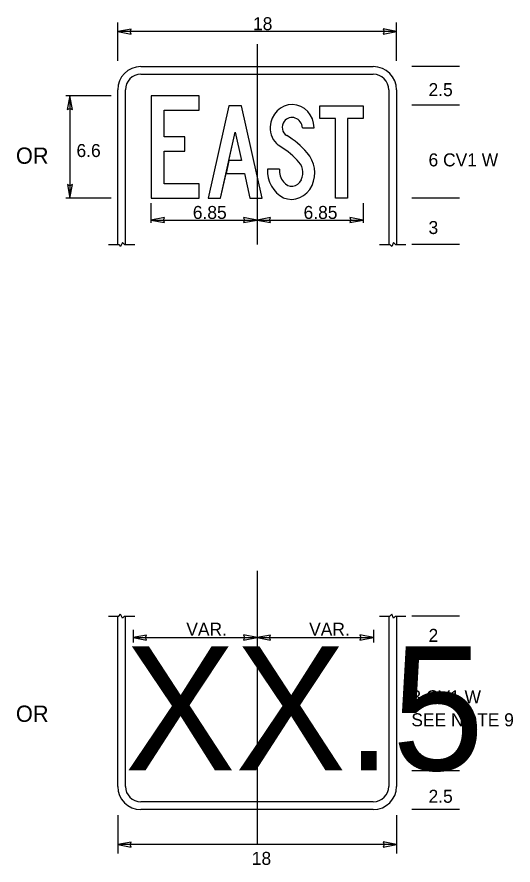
# Model space of a CAD drawing. Extents: x 56108 to 56738, y 11696 to 12112.
# Drawn here: x 56631.7 to 56738.5, y 11927.4 to 12110.1 of the extents above; entities that cross this region are included whole.
import ezdxf

# ---------------------------------------------------------------- set-up
doc = ezdxf.new("R2010")
doc.units = 0
for name, color, linetype in [('CL_dp', 7, 'Continuous'), ('GSDims', 7, 'Continuous'), ('SignPanel', 7, 'Continuous')]:
    doc.layers.add(name, color=color, linetype=linetype)

msp = doc.modelspace()

# ---------------------------------------------------------------- linework, layer by layer
at = {"layer": 'CL_dp'}
for p, q in [((56683.41, 12104.19), (56683.41, 12061.05)), ((56683.41, 11990.78), (56683.41, 11931.84))]:
    msp.add_line(p, q, dxfattribs=at)
at = {"layer": 'GSDims'}
for p, q in [((56653.41, 12100.62), (56653.41, 12108.84)), ((56713.41, 12100.62), (56713.41, 12108.84)), ((56656.31, 12107.46), (56653.41, 12106.92)), ((56713.41, 12106.92), (56653.41, 12106.92)), ((56653.41, 12106.92), (56656.31, 12106.36)), ((56656.09, 12106.92), (56656.31, 12107.46)), ((56656.31, 12106.36), (56656.09, 12106.92)), ((56713.41, 12106.92), (56710.51, 12107.48)), ((56710.51, 12107.48), (56710.73, 12106.92)), ((56710.73, 12106.92), (56710.51, 12106.38)), ((56710.51, 12106.38), (56713.41, 12106.92)), ((56726.96, 12099.38), (56716.67, 12099.38)), ((56652, 12093.05), (56642.26, 12093.05)), ((56643.13, 12093.05), (56642.57, 12090.15)), ((56643.13, 12093.05), (56643.13, 12071.05)), ((56643.67, 12090.15), (56643.13, 12093.05)), ((56642.57, 12090.15), (56643.13, 12090.37)), ((56643.13, 12090.37), (56643.67, 12090.15)), ((56726.96, 12091.05), (56716.67, 12091.05)), ((56643.13, 12073.73), (56642.59, 12073.95)), ((56642.59, 12073.95), (56643.13, 12071.05)), ((56643.13, 12071.05), (56643.69, 12073.95)), ((56643.69, 12073.95), (56643.13, 12073.73)), ((56652, 12071.05), (56642.26, 12071.05)), ((56726.96, 12071.05), (56716.67, 12071.05)), ((56660.58, 12069.96), (56660.58, 12065.71)), ((56706.25, 12069.96), (56706.25, 12065.71)), ((56663.48, 12066.87), (56660.58, 12066.33)), ((56663.26, 12066.33), (56663.48, 12066.87)), ((56683.41, 12066.33), (56680.51, 12066.89)), ((56680.51, 12066.89), (56680.73, 12066.33)), ((56686.31, 12066.87), (56683.41, 12066.33)), ((56686.09, 12066.33), (56686.31, 12066.87)), ((56706.25, 12066.33), (56703.35, 12066.89)), ((56703.35, 12066.89), (56703.57, 12066.33)), ((56660.58, 12066.33), (56683.41, 12066.33)), ((56660.58, 12066.33), (56663.48, 12065.77)), ((56663.48, 12065.77), (56663.26, 12066.33)), ((56680.73, 12066.33), (56680.51, 12065.79)), ((56680.51, 12065.79), (56683.41, 12066.33)), ((56683.41, 12066.33), (56706.25, 12066.33)), ((56683.41, 12066.33), (56686.31, 12065.77)), ((56686.31, 12065.77), (56686.09, 12066.33)), ((56703.57, 12066.33), (56703.35, 12065.79)), ((56703.35, 12065.79), (56706.25, 12066.33)), ((56726.96, 12061.05), (56716.67, 12061.05)), ((56726.96, 11981.05), (56716.67, 11981.05)), ((56656.74, 11978.07), (56656.74, 11975.38)), ((56708.43, 11978.07), (56708.43, 11975.38)), ((56659.64, 11976.96), (56656.74, 11976.42)), ((56656.74, 11976.42), (56683.41, 11976.42)), ((56656.74, 11976.42), (56659.64, 11975.86)), ((56659.42, 11976.42), (56659.64, 11976.96)), ((56659.64, 11975.86), (56659.42, 11976.42)), ((56683.41, 11976.42), (56680.51, 11976.98)), ((56680.51, 11976.98), (56680.73, 11976.42)), ((56680.73, 11976.42), (56680.51, 11975.88)), ((56680.51, 11975.88), (56683.41, 11976.42)), ((56686.31, 11976.96), (56683.41, 11976.42)), ((56683.41, 11976.42), (56708.43, 11976.42)), ((56683.41, 11976.42), (56686.31, 11975.86)), ((56686.09, 11976.42), (56686.31, 11976.96)), ((56686.31, 11975.86), (56686.09, 11976.42)), ((56708.43, 11976.42), (56705.53, 11976.98)), ((56705.53, 11976.98), (56705.75, 11976.42)), ((56705.75, 11976.42), (56705.53, 11975.88)), ((56705.53, 11975.88), (56708.43, 11976.42)), ((56726.96, 11974.38), (56716.67, 11974.38)), ((56726.96, 11947.71), (56716.67, 11947.71)), ((56726.96, 11939.38), (56716.67, 11939.38)), ((56653.41, 11938.14), (56653.41, 11929.91)), ((56713.41, 11938.14), (56713.41, 11929.91)), ((56656.31, 11932.38), (56653.41, 11931.84)), ((56713.41, 11931.84), (56653.41, 11931.84)), ((56653.41, 11931.84), (56656.31, 11931.28)), ((56656.09, 11931.84), (56656.31, 11932.38)), ((56656.31, 11931.28), (56656.09, 11931.84)), ((56713.41, 11931.84), (56710.51, 11932.4)), ((56710.51, 11932.4), (56710.73, 11931.84)), ((56710.73, 11931.84), (56710.51, 11931.3)), ((56710.51, 11931.3), (56713.41, 11931.84))]:
    msp.add_line(p, q, dxfattribs=at)
at = {"layer": 'SignPanel'}
for p, q in [((56693.15, 12086.17), (56695.69, 12086.17)), ((56693.15, 12086.17), (56695.69, 12086.17)), ((56693.15, 12086.17), (56695.69, 12086.17)), ((56688.21, 12077.3), (56685.62, 12077.3)), ((56688.21, 12077.3), (56685.62, 12077.3)), ((56688.21, 12077.3), (56685.62, 12077.3)), ((56654.45, 12061.46), (56654.04, 12060.63)), ((56654.45, 12061.46), (56654.87, 12061.05)), ((56712.79, 12061.46), (56712.37, 12060.63)), ((56712.79, 12061.46), (56713.2, 12061.05)), ((56651.41, 12061.05), (56653.63, 12061.05)), ((56653.63, 12061.05), (56654.04, 12060.63)), ((56654.87, 12061.05), (56657.08, 12061.05)), ((56709.75, 12061.05), (56711.96, 12061.05)), ((56711.96, 12061.05), (56712.37, 12060.63)), ((56713.2, 12061.05), (56715.41, 12061.05)), ((56651.41, 11981.05), (56653.63, 11981.05)), ((56653.63, 11981.05), (56654.04, 11981.46)), ((56654.45, 11980.63), (56654.04, 11981.46)), ((56654.45, 11980.63), (56654.87, 11981.05)), ((56654.87, 11981.05), (56657.08, 11981.05)), ((56709.75, 11981.05), (56711.96, 11981.05)), ((56711.96, 11981.05), (56712.37, 11981.46)), ((56712.79, 11980.63), (56712.37, 11981.46)), ((56712.79, 11980.63), (56713.2, 11981.05)), ((56713.2, 11981.05), (56715.41, 11981.05))]:
    msp.add_line(p, q, dxfattribs=at)
for points in [[(56658.41, 12099.38), (56708.41, 12099.38)], [(56658.41, 12097.71), (56708.41, 12097.71)], [(56653.41, 12061.05), (56653.41, 12094.38)], [(56655.08, 12061.05), (56655.08, 12094.38)], [(56711.75, 12094.38), (56711.75, 12061.05)], [(56713.41, 12094.38), (56713.41, 12061.05)], [(56653.41, 11944.38), (56653.41, 11981.05)], [(56655.08, 11944.38), (56655.08, 11981.05)], [(56711.75, 11981.05), (56711.75, 11944.38)], [(56713.41, 11981.05), (56713.41, 11944.38)], [(56708.41, 11941.05), (56658.41, 11941.05)], [(56708.41, 11939.38), (56658.41, 11939.38)]]:
    msp.add_lwpolyline(points, dxfattribs=at)
for points in [[(56663.44, 12074.14), (56663.44, 12081.19), (56667.87, 12081.19), (56667.87, 12084.27), (56663.44, 12084.27), (56663.44, 12089.99), (56670.93, 12089.99), (56670.93, 12093.08), (56660.61, 12093.08), (56660.61, 12071.06), (56670.93, 12071.06), (56670.93, 12074.14)], [(56663.44, 12074.14), (56663.44, 12081.19), (56667.87, 12081.19), (56667.87, 12084.27), (56663.44, 12084.27), (56663.44, 12089.99), (56670.93, 12089.99), (56670.93, 12093.08), (56660.61, 12093.08), (56660.61, 12071.06), (56670.93, 12071.06), (56670.93, 12074.14)], [(56663.44, 12074.14), (56663.44, 12081.19), (56667.87, 12081.19), (56667.87, 12084.27), (56663.44, 12084.27), (56663.44, 12089.99), (56670.93, 12089.99), (56670.93, 12093.08), (56660.61, 12093.08), (56660.61, 12071.06), (56670.93, 12071.06), (56670.93, 12074.14)], [(56680.7, 12076.39), (56681.88, 12071.06), (56684.52, 12071.06), (56680.08, 12090.95), (56677.34, 12090.95), (56672.91, 12071.06), (56675.54, 12071.06), (56676.73, 12076.39)], [(56677.35, 12079.17), (56676.73, 12076.39), (56680.7, 12076.39), (56681.88, 12071.06), (56684.52, 12071.06), (56680.08, 12090.95), (56677.34, 12090.95), (56672.91, 12071.06), (56675.54, 12071.06), (56678.71, 12085.29), (56680.08, 12079.17)], [(56677.35, 12079.17), (56676.73, 12076.39), (56680.7, 12076.39), (56681.88, 12071.06), (56684.52, 12071.06), (56680.08, 12090.95), (56677.34, 12090.95), (56672.91, 12071.06), (56675.54, 12071.06), (56678.71, 12085.29), (56680.08, 12079.17)], [(56700.3, 12088.17), (56696.92, 12088.17), (56696.92, 12090.95), (56706.25, 12090.95), (56706.25, 12088.17), (56702.86, 12088.17), (56702.86, 12071.06), (56700.3, 12071.06)], [(56700.3, 12088.17), (56696.92, 12088.17), (56696.92, 12090.95), (56706.25, 12090.95), (56706.25, 12088.17), (56702.86, 12088.17), (56702.86, 12071.06), (56700.3, 12071.06)], [(56700.3, 12088.17), (56696.92, 12088.17), (56696.92, 12090.95), (56706.25, 12090.95), (56706.25, 12088.17), (56702.86, 12088.17), (56702.86, 12071.06), (56700.3, 12071.06)], [(56678.71, 12085.29), (56680.08, 12079.17), (56677.35, 12079.17)]]:
    msp.add_lwpolyline(points, close=True, dxfattribs=at)
for centre, radius, start, end in [((56658.41, 12094.38), 5, 90, 180), ((56658.41, 12094.38), 3.33, 90, 180), ((56708.41, 12094.38), 5, 0, 90), ((56708.41, 12094.38), 3.33, 0, 90), ((56658.41, 11944.38), 5, 180, 270), ((56658.41, 11944.38), 3.33, 180, 270), ((56708.41, 11944.38), 5, 270, 360), ((56708.41, 11944.38), 3.33, 270, 360)]:
    msp.add_arc(centre, radius, start, end, dxfattribs=at)
for centre, major_axis, start_param, end_param in [((56690.95, 12086.05), (0, 5.16), 4.736267, 7.790596), ((56690.95, 12086.05), (0, 5.16), 4.736267, 7.790596), ((56690.95, 12086.05), (0, 5.16), 4.736267, 7.790596), ((56690.92, 12085.99), (0, 2.43), 4.786904, 7.140738), ((56690.92, 12085.99), (0, 2.43), 4.786904, 7.140738), ((56690.92, 12085.99), (0, 2.43), 4.786904, 7.140738), ((56690.65, 12086.29), (0, 2), 0.87378, 2.656959), ((56690.65, 12086.29), (0, 2), 0.87378, 2.656959), ((56690.65, 12086.29), (0, 2), 0.87378, 2.656959), ((56690.47, 12086.21), (0, 4.63), 1.534831, 2.511766), ((56690.47, 12086.21), (0, 4.63), 1.534831, 2.511766), ((56690.47, 12086.21), (0, 4.63), 1.534831, 2.511766), ((56681.36, 12067.78), (0, 19.09), 5.462886, 5.782242), ((56681.36, 12067.78), (0, 19.09), 5.462886, 5.782242), ((56681.36, 12067.78), (0, 19.09), 5.462886, 5.782242), ((56679.14, 12064.74), (0, 20.15), 5.515137, 5.786988), ((56679.14, 12064.74), (0, 20.15), 5.515137, 5.786988), ((56679.14, 12064.74), (0, 20.15), 5.515137, 5.786988), ((56690.14, 12076.49), (0, 6.17), 4.260987, 5.485755), ((56690.14, 12076.49), (0, 6.17), 4.260987, 5.485755), ((56690.14, 12076.49), (0, 6.17), 4.260987, 5.485755), ((56690.09, 12076.49), (0, 3.44), 4.254409, 5.632398), ((56690.09, 12076.49), (0, 3.44), 4.254409, 5.632398), ((56690.09, 12076.49), (0, 3.44), 4.254409, 5.632398), ((56691.6, 12077.01), (0, 6.5), 1.526364, 2.701682), ((56691.6, 12077.01), (0, 6.5), 1.526364, 2.701682), ((56691.6, 12077.01), (0, 6.5), 1.526364, 2.701682), ((56691.84, 12077.12), (0, 3.96), 1.524757, 2.28214), ((56691.84, 12077.12), (0, 3.96), 1.524757, 2.28214), ((56691.84, 12077.12), (0, 3.96), 1.524757, 2.28214), ((56690.88, 12076.14), (0, 2.53), 2.261787, 4.23006), ((56690.88, 12076.14), (0, 2.53), 2.261787, 4.23006), ((56690.88, 12076.14), (0, 2.53), 2.261787, 4.23006), ((56690.78, 12076.2), (0, 5.41), 2.786047, 4.251692), ((56690.78, 12076.2), (0, 5.41), 2.786047, 4.251692), ((56690.78, 12076.2), (0, 5.41), 2.786047, 4.251692)]:
    msp.add_ellipse(centre, major_axis=major_axis, ratio=0.91923, start_param=start_param, end_param=end_param, dxfattribs=at)

# ---------------------------------------------------------------- texts
at = {"layer": 'GSDims'}
for s, height, p in [('18', 2.8, (56682.53, 12107.22)), ('2.5', 2.8, (56720.3, 12093.01)), ('OR', 3.5, (56631.52, 12078.45)), ('6.6', 2.8, (56644.55, 12079.9)), ('6 CV1 W', 2.8, (56720.3, 12077.89)), ('6.85', 2.8, (56669.58, 12066.57)), ('6.85', 2.8, (56693.41, 12066.57)), ('3', 2.8, (56720.3, 12063.32)), ('VAR.', 2.8, (56668.18, 11976.82)), ('VAR.', 2.8, (56694.61, 11976.82)), ('2', 2.8, (56720.3, 11975.49)), ('8 CV1 W', 2.8, (56716.6, 11962.26)), ('OR', 3.5, (56631.52, 11958.27)), ('SEE NOTE 9', 2.8, (56716.6, 11957.31)), ('2.5', 2.8, (56720.3, 11940.84)), ('18', 2.8, (56682.27, 11927.47))]:
    msp.add_text(s, height=height, dxfattribs=at).set_placement(p)
at = {"layer": 'SignPanel'}
msp.add_text('XX.5', height=26.667, dxfattribs=at).set_placement((56654.95, 11947.85))

doc.saveas('drawing.dxf')
